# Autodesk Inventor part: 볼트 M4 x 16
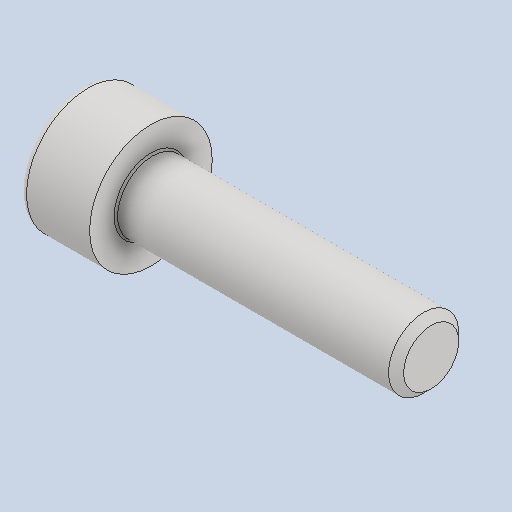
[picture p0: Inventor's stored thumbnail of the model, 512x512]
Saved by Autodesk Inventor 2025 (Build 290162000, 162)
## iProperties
Created: 2024-07
Part Number: 볼트 M4 x 16
Material: 스테인리스강
Description: 6각 소켓 머리 캡 나사
Document SubType Name: Modeling
Designer: myung
Density: 8.08 g/cm^3
Appearance: 기본값
Author: jhkim
Sending System: Autodesk Inventor 2025
Preprocessor: ST-DEVELOPER v20
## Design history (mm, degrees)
feature "Solid1"
node "솔리드1"
